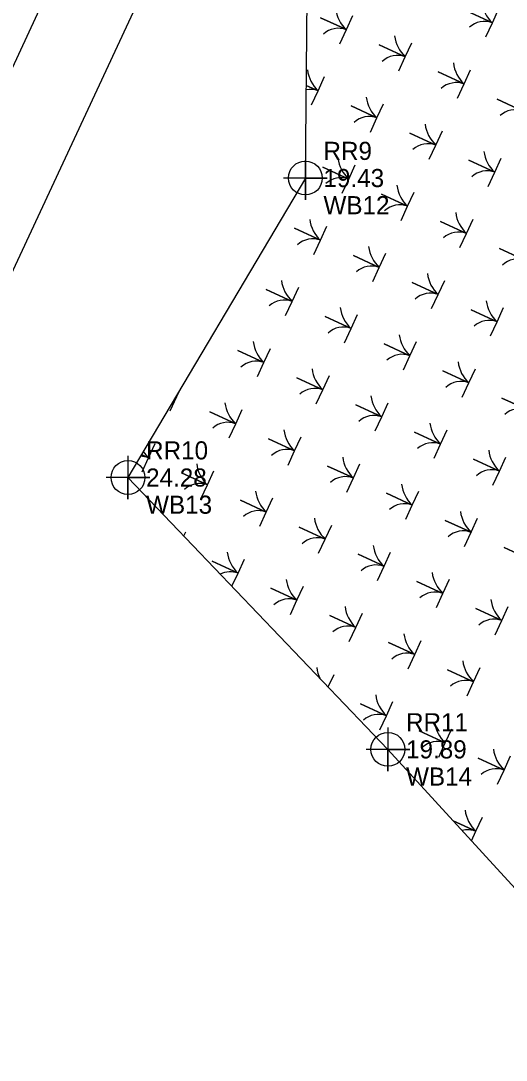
# Model space of a CAD drawing. Extents: x 2532037 to 2533565, y 713396 to 716867.
# Drawn here: x 2532831.4 to 2532898.3, y 715371.9 to 715515.5 of the extents above; entities that cross this region are included whole.
import ezdxf

# ---------------------------------------------------------------- set-up
doc = ezdxf.new("R2010")
doc.units = 0
for name, color, linetype in [('Exist Environmental Wetland Boundary', 7, 'Continuous'), ('Exist Environmental Wetland Boundary Cogo Comment', 7, 'Continuous'), ('Exist Environmental Wetland Boundary Cogo Elevation', 7, 'Continuous'), ('Exist Environmental Wetland Boundary Cogo Number', 7, 'Continuous'), ('Exist Environmental Wetland Boundary Cogo Point CELL', 7, 'Continuous'), ('Exist Hydro Stream or Body of Water', 7, 'Continuous'), ('Exist Right of Way Line', 7, 'Continuous'), ('Scratch_Level_1', 7, 'Continuous')]:
    doc.layers.add(name, color=color, linetype=linetype)

msp = doc.modelspace()

# ---------------------------------------------------------------- linework, layer by layer
at = {"layer": 'Exist Environmental Wetland Boundary'}
for p, q in [((2532870.62, 715493.74), (2532871.25, 715556.68)), ((2532870.62, 715493.74), (2532846.15, 715452.38)), ((2532882.01, 715414.84), (2532846.15, 715452.38)), ((2532882.01, 715414.84), (2532902.53, 715392.38))]:
    msp.add_line(p, q, dxfattribs=at)
at = {"layer": 'Exist Environmental Wetland Boundary Cogo Point CELL'}
for points in [[(2532870.62, 715496.74), (2532870.62, 715490.74), (2532870.62, 715493.74), (2532873.62, 715493.74), (2532867.62, 715493.74)], [(2532846.15, 715455.38), (2532846.15, 715449.38), (2532846.15, 715452.38), (2532849.15, 715452.38), (2532843.15, 715452.38)], [(2532882.01, 715417.84), (2532882.01, 715411.84), (2532882.01, 715414.84), (2532885.01, 715414.84), (2532879.01, 715414.84)]]:
    msp.add_lwpolyline(points, dxfattribs=at)
for centre in [(2532870.62, 715493.74), (2532846.15, 715452.38), (2532882.01, 715414.84)]:
    msp.add_circle(centre, 2.34, dxfattribs=at)
at = {"layer": 'Exist Hydro Stream or Body of Water'}
msp.add_lwpolyline([(2532802.27, 715448.15), (2532818.09, 715482.8), (2532835.7, 715520.84), (2532847.1, 715539.97), (2532855.45, 715551.87), (2532861.07, 715556.64), (2532861.28, 715557.62), (2532865.35, 715565.35), (2532877.49, 715580.36), (2532883.64, 715600.48), (2532881.52, 715610.88), (2532882.29, 715614.35)], dxfattribs=at)
at = {"layer": 'Exist Right of Way Line'}
msp.add_line((2532748.02, 715304.21), (2532950.04, 715738.43), dxfattribs=at)
at = {"layer": 'Scratch_Level_1'}
for p, q in [((2532853.85, 715444.31), (2532854.11, 715444.88)), ((2532873.78, 715423.46), (2532874.58, 715425.19))]:
    msp.add_line(p, q, dxfattribs=at)
for points in [[(2532895.52, 715513.22), (2532896.42, 715515.18), (2532892.84, 715516.83), (2532896.42, 715515.18), (2532897.32, 715517.13)], [(2532875.38, 715512.28), (2532876.28, 715514.23), (2532872.69, 715515.88), (2532876.28, 715514.23), (2532877.18, 715516.18)], [(2532883.5, 715508.53), (2532884.4, 715510.48), (2532880.82, 715512.13), (2532884.4, 715510.48), (2532885.3, 715512.43)], [(2532870.75, 715506.54), (2532872.38, 715505.79), (2532873.28, 715507.74)], [(2532891.62, 715504.78), (2532892.52, 715506.73), (2532888.94, 715508.39), (2532892.52, 715506.73), (2532893.42, 715508.68)], [(2532871.48, 715503.83), (2532872.38, 715505.79), (2532870.75, 715506.54)], [(2532899.74, 715501.03), (2532900.64, 715502.98), (2532897.06, 715504.64), (2532900.64, 715502.98), (2532901.54, 715504.93)], [(2532879.6, 715500.08), (2532880.5, 715502.04), (2532876.92, 715503.69), (2532880.5, 715502.04), (2532881.4, 715503.99)], [(2532887.72, 715496.33), (2532888.62, 715498.29), (2532885.04, 715499.94), (2532888.62, 715498.29), (2532889.52, 715500.24)], [(2532895.84, 715492.59), (2532896.74, 715494.54), (2532893.16, 715496.19), (2532896.74, 715494.54), (2532897.64, 715496.49)], [(2532875.7, 715491.64), (2532876.6, 715493.59), (2532873.02, 715495.25), (2532876.6, 715493.59), (2532877.5, 715495.54)], [(2532883.82, 715487.89), (2532884.72, 715489.84), (2532881.14, 715491.5), (2532884.72, 715489.84), (2532885.62, 715491.8)], [(2532891.94, 715484.14), (2532892.84, 715486.09), (2532889.26, 715487.75), (2532892.84, 715486.09), (2532893.75, 715488.05)], [(2532871.8, 715483.2), (2532872.7, 715485.15), (2532869.12, 715486.8), (2532872.7, 715485.15), (2532873.6, 715487.1)], [(2532879.92, 715479.45), (2532880.82, 715481.4), (2532877.24, 715483.05), (2532880.82, 715481.4), (2532881.73, 715483.35)], [(2532900.06, 715480.39), (2532900.97, 715482.34), (2532897.38, 715484), (2532900.97, 715482.34), (2532901.87, 715484.3)], [(2532888.04, 715475.7), (2532888.95, 715477.65), (2532885.36, 715479.3), (2532888.95, 715477.65), (2532889.85, 715479.6)], [(2532867.9, 715474.75), (2532868.8, 715476.7), (2532865.22, 715478.36), (2532868.8, 715476.7), (2532869.71, 715478.66)], [(2532876.02, 715471), (2532876.93, 715472.95), (2532873.34, 715474.61), (2532876.93, 715472.95), (2532877.83, 715474.91)], [(2532896.17, 715471.95), (2532897.07, 715473.9), (2532893.49, 715475.55), (2532897.07, 715473.9), (2532897.97, 715475.85)], [(2532884.15, 715467.25), (2532885.05, 715469.2), (2532881.47, 715470.86), (2532885.05, 715469.2), (2532885.95, 715471.16)], [(2532864, 715466.31), (2532864.91, 715468.26), (2532861.32, 715469.91), (2532864.91, 715468.26), (2532865.81, 715470.21)], [(2532872.13, 715462.56), (2532873.03, 715464.51), (2532869.45, 715466.16), (2532873.03, 715464.51), (2532873.93, 715466.46)], [(2532892.27, 715463.5), (2532893.17, 715465.46), (2532889.59, 715467.11), (2532893.17, 715465.46), (2532894.07, 715467.41)], [(2532851.98, 715461.61), (2532852.89, 715463.56), (2532852.79, 715463.61)], [(2532852.79, 715463.61), (2532852.89, 715463.56), (2532853.3, 715464.46)], [(2532900.39, 715459.75), (2532901.29, 715461.71), (2532897.71, 715463.36), (2532901.29, 715461.71), (2532902.19, 715463.66)], [(2532860.11, 715457.86), (2532861.01, 715459.81), (2532857.43, 715461.47), (2532861.01, 715459.81), (2532861.91, 715461.77)], [(2532880.25, 715458.81), (2532881.15, 715460.76), (2532877.57, 715462.41), (2532881.15, 715460.76), (2532882.05, 715462.71)], [(2532888.37, 715455.06), (2532889.27, 715457.01), (2532885.69, 715458.66), (2532889.27, 715457.01), (2532890.17, 715458.96)], [(2532868.23, 715454.11), (2532869.13, 715456.07), (2532865.55, 715457.72), (2532869.13, 715456.07), (2532870.03, 715458.02)], [(2532848.03, 715455.56), (2532848.99, 715455.12), (2532849.89, 715457.07)], [(2532848.09, 715453.17), (2532848.99, 715455.12), (2532848.03, 715455.56)], [(2532896.49, 715451.31), (2532897.39, 715453.26), (2532893.81, 715454.92), (2532897.39, 715453.26), (2532898.29, 715455.21)], [(2532856.21, 715449.42), (2532857.11, 715451.37), (2532853.53, 715453.02), (2532857.11, 715451.37), (2532858.01, 715453.32)], [(2532876.35, 715450.36), (2532877.25, 715452.32), (2532873.67, 715453.97), (2532877.25, 715452.32), (2532878.15, 715454.27)], [(2532884.47, 715446.61), (2532885.37, 715448.57), (2532881.79, 715450.22), (2532885.37, 715448.57), (2532886.27, 715450.52)], [(2532864.33, 715445.67), (2532865.23, 715447.62), (2532861.65, 715449.27), (2532865.23, 715447.62), (2532866.13, 715449.57)], [(2532892.59, 715442.86), (2532893.49, 715444.82), (2532889.91, 715446.47), (2532893.49, 715444.82), (2532894.39, 715446.77)], [(2532872.45, 715441.92), (2532873.35, 715443.87), (2532869.77, 715445.53), (2532873.35, 715443.87), (2532874.25, 715445.82)], [(2532880.57, 715438.17), (2532881.47, 715440.12), (2532877.89, 715441.78), (2532881.47, 715440.12), (2532882.37, 715442.07)], [(2532900.71, 715439.12), (2532901.61, 715441.07), (2532898.03, 715442.72), (2532901.61, 715441.07), (2532902.52, 715443.02)], [(2532860.49, 715437.36), (2532861.33, 715439.18), (2532857.75, 715440.83), (2532861.33, 715439.18), (2532862.23, 715441.13)], [(2532868.55, 715433.47), (2532869.45, 715435.43), (2532865.87, 715437.08), (2532869.45, 715435.43), (2532870.35, 715437.38)], [(2532888.69, 715434.42), (2532889.59, 715436.37), (2532886.01, 715438.03), (2532889.59, 715436.37), (2532890.5, 715438.33)], [(2532896.81, 715430.67), (2532897.72, 715432.62), (2532894.13, 715434.28), (2532897.72, 715432.62), (2532898.62, 715434.58)], [(2532876.67, 715429.73), (2532877.57, 715431.68), (2532873.99, 715433.33), (2532877.57, 715431.68), (2532878.48, 715433.63)], [(2532884.79, 715425.98), (2532885.7, 715427.93), (2532882.11, 715429.58), (2532885.7, 715427.93), (2532886.6, 715429.88)], [(2532892.92, 715422.23), (2532893.82, 715424.18), (2532890.24, 715425.83), (2532893.82, 715424.18), (2532894.72, 715426.13)], [(2532880.9, 715417.53), (2532881.8, 715419.48), (2532878.22, 715421.14), (2532881.8, 715419.48), (2532882.7, 715421.44)], [(2532889.02, 715413.78), (2532889.92, 715415.73), (2532886.34, 715417.39), (2532889.92, 715415.73), (2532890.82, 715417.69)], [(2532897.14, 715410.03), (2532898.04, 715411.99), (2532894.46, 715413.64), (2532898.04, 715411.99), (2532898.94, 715413.94)], [(2532891.01, 715404.99), (2532894.14, 715403.54), (2532895.04, 715405.49)], [(2532893.53, 715402.22), (2532894.14, 715403.54), (2532891.01, 715404.99)]]:
    msp.add_lwpolyline(points, dxfattribs=at)
for centre, radius, start, end in [((2532899.71, 715518.68), 4.81, 187.3464, 226.8412), ((2532879.56, 715517.74), 4.81, 187.3464, 226.8412), ((2532895.33, 715512.3), 3.07, 69.3593, 132.7539), ((2532875.19, 715511.35), 3.07, 69.3593, 132.7539), ((2532887.69, 715513.99), 4.81, 187.3464, 226.8412), ((2532883.31, 715507.6), 3.07, 69.3593, 132.7539), ((2532895.81, 715510.24), 4.81, 187.3464, 226.8412), ((2532875.67, 715509.29), 4.81, 187.3464, 226.8412), ((2532891.44, 715503.85), 3.07, 69.3593, 132.7539), ((2532871.29, 715502.91), 3.07, 69.3593, 100.3208), ((2532883.79, 715505.54), 4.81, 187.3464, 226.8412), ((2532879.42, 715499.16), 3.07, 69.3593, 132.7539), ((2532899.56, 715500.1), 3.07, 69.3593, 132.7539), ((2532891.91, 715501.79), 4.81, 187.3464, 226.8412), ((2532887.54, 715495.41), 3.07, 69.3593, 132.7539), ((2532879.89, 715497.1), 4.81, 187.3464, 226.8412), ((2532900.03, 715498.04), 4.81, 187.3464, 226.8412), ((2532895.66, 715491.66), 3.07, 69.3593, 132.7539), ((2532875.52, 715490.71), 3.07, 69.3593, 132.7539), ((2532888.01, 715493.35), 4.81, 187.3464, 226.8412), ((2532883.64, 715486.97), 3.07, 69.3593, 132.7539), ((2532896.13, 715489.6), 4.81, 187.3464, 226.8412), ((2532875.99, 715488.65), 4.81, 187.3464, 226.8412), ((2532891.76, 715483.22), 3.07, 69.3593, 132.7539), ((2532871.62, 715482.27), 3.07, 69.3593, 132.7539), ((2532884.11, 715484.9), 4.81, 187.3464, 226.8412), ((2532899.88, 715479.47), 3.07, 69.3593, 132.7539), ((2532879.74, 715478.52), 3.07, 69.3593, 132.7539), ((2532892.23, 715481.15), 4.81, 187.3464, 226.8412), ((2532872.09, 715480.21), 4.81, 187.3464, 226.8412), ((2532887.86, 715474.77), 3.07, 69.3593, 132.7539), ((2532867.72, 715473.83), 3.07, 69.3593, 132.7539), ((2532900.35, 715477.41), 4.81, 187.3464, 226.8412), ((2532880.21, 715476.46), 4.81, 187.3464, 226.8412), ((2532895.98, 715471.02), 3.07, 69.3593, 132.7539), ((2532875.84, 715470.08), 3.07, 69.3593, 132.7539), ((2532888.33, 715472.71), 4.81, 187.3464, 226.8412), ((2532868.19, 715471.76), 4.81, 187.3464, 226.8412), ((2532883.96, 715466.33), 3.07, 69.3593, 132.7539), ((2532863.82, 715465.38), 3.07, 69.3593, 132.7539), ((2532896.46, 715468.96), 4.81, 187.3464, 226.8412), ((2532876.31, 715468.02), 4.81, 187.3464, 226.8412), ((2532871.94, 715461.63), 3.07, 69.3593, 132.7539), ((2532892.08, 715462.58), 3.07, 69.3593, 132.7539), ((2532851.8, 715460.69), 3.07, 69.3593, 71.2706), ((2532856.17, 715467.07), 4.81, 225.6081, 226.8412), ((2532884.44, 715464.27), 4.81, 187.3464, 226.8412), ((2532864.29, 715463.32), 4.81, 187.3464, 226.8412), ((2532900.21, 715458.83), 3.07, 69.3593, 132.7539), ((2532880.06, 715457.88), 3.07, 69.3593, 132.7539), ((2532859.92, 715456.94), 3.07, 69.3593, 132.7539), ((2532872.42, 715459.57), 4.81, 187.3464, 226.8412), ((2532892.56, 715460.52), 4.81, 187.3464, 226.8412), ((2532852.27, 715458.63), 4.81, 213.6275, 226.8412), ((2532868.05, 715453.19), 3.07, 69.3593, 132.7539), ((2532888.19, 715454.13), 3.07, 69.3593, 132.7539), ((2532900.68, 715456.77), 4.81, 187.3464, 226.8412), ((2532847.9, 715452.24), 3.07, 69.3593, 90.2442), ((2532880.54, 715455.82), 4.81, 187.3464, 226.8412), ((2532860.4, 715454.88), 4.81, 187.3464, 226.8412), ((2532896.31, 715450.38), 3.07, 69.3593, 132.7539), ((2532876.17, 715449.44), 3.07, 69.3593, 132.7539), ((2532856.03, 715448.49), 3.07, 69.3593, 132.7539), ((2532868.52, 715451.13), 4.81, 187.3464, 226.8412), ((2532888.66, 715452.07), 4.81, 187.3464, 226.8412), ((2532864.15, 715444.74), 3.07, 69.3593, 132.7539), ((2532884.29, 715445.69), 3.07, 69.3593, 132.7539), ((2532896.78, 715448.32), 4.81, 187.3464, 226.8412), ((2532876.64, 715447.38), 4.81, 187.3464, 226.8412), ((2532892.41, 715441.94), 3.07, 69.3593, 132.7539), ((2532872.27, 715440.99), 3.07, 69.3593, 132.7539), ((2532864.62, 715442.68), 4.81, 187.3464, 226.8412), ((2532884.76, 715443.63), 4.81, 187.3464, 226.8412), ((2532880.39, 715437.24), 3.07, 69.3593, 132.7539), ((2532860.25, 715436.3), 3.07, 69.3593, 116.4375), ((2532892.88, 715439.88), 4.81, 187.3464, 226.8412), ((2532872.74, 715438.93), 4.81, 187.3464, 226.8412), ((2532888.51, 715433.5), 3.07, 69.3593, 132.7539), ((2532868.37, 715432.55), 3.07, 69.3593, 132.7539), ((2532880.86, 715435.18), 4.81, 187.3464, 226.8412), ((2532901, 715436.13), 4.81, 187.3464, 226.8412), ((2532876.49, 715428.8), 3.07, 69.3593, 132.7539), ((2532896.63, 715429.75), 3.07, 69.3593, 132.7539), ((2532888.98, 715431.43), 4.81, 187.3464, 226.8412), ((2532884.61, 715425.05), 3.07, 69.3593, 132.7539), ((2532876.96, 715426.74), 4.81, 187.3464, 205.6983), ((2532897.1, 715427.68), 4.81, 187.3464, 226.8412), ((2532892.73, 715421.3), 3.07, 69.3593, 132.7539), ((2532885.09, 715422.99), 4.81, 187.3464, 226.8412), ((2532880.71, 715416.61), 3.07, 69.3593, 132.7539), ((2532893.21, 715419.24), 4.81, 187.3464, 226.8412), ((2532888.84, 715412.86), 3.07, 69.3593, 132.7539), ((2532901.33, 715415.49), 4.81, 187.3464, 226.8412), ((2532896.96, 715409.11), 3.07, 69.3593, 132.7539), ((2532897.43, 715407.05), 4.81, 187.3464, 226.8412), ((2532893.06, 715400.66), 3.07, 69.3593, 105.244)]:
    msp.add_arc(centre, radius, start, end, dxfattribs=at)

# ---------------------------------------------------------------- texts
at = {"layer": 'Exist Environmental Wetland Boundary Cogo Comment'}
for s, p in [('WB12', (2532873.12, 715488.74)), ('WB13', (2532848.65, 715447.38)), ('WB14', (2532884.51, 715409.84))]:
    msp.add_text(s, height=2.5, dxfattribs=at).set_placement(p)
at = {"layer": 'Exist Environmental Wetland Boundary Cogo Elevation'}
for s, p in [('19.43', (2532873.12, 715492.49)), ('24.28', (2532848.65, 715451.13)), ('19.89', (2532884.51, 715413.59))]:
    msp.add_text(s, height=2.5, dxfattribs=at).set_placement(p)
at = {"layer": 'Exist Environmental Wetland Boundary Cogo Number'}
for s, p in [('RR9', (2532873.12, 715496.24)), ('RR10', (2532848.65, 715454.88)), ('RR11', (2532884.51, 715417.34))]:
    msp.add_text(s, height=2.5, dxfattribs=at).set_placement(p)

doc.saveas('drawing.dxf')
